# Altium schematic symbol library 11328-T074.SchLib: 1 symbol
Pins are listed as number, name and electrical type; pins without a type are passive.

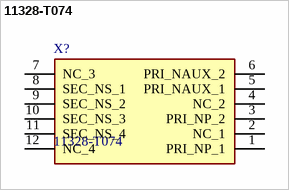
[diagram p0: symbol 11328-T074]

## 11328-T074
designator X?
Power Transformers Flyback Transformer for LT8316; Manufacturer_Name: Sumida; Geometry.Height: 23.5mm
footprint 11328T074
pins: 1 PRI_NP_1, 2 NC_1, 3 PRI_NP_2, 4 NC_2, 5 PRI_NAUX_1, 6 PRI_NAUX_2, 7 NC_3, 8 SEC_NS_1, 9 SEC_NS_2, 10 SEC_NS_3, 11 SEC_NS_4, 12 NC_4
